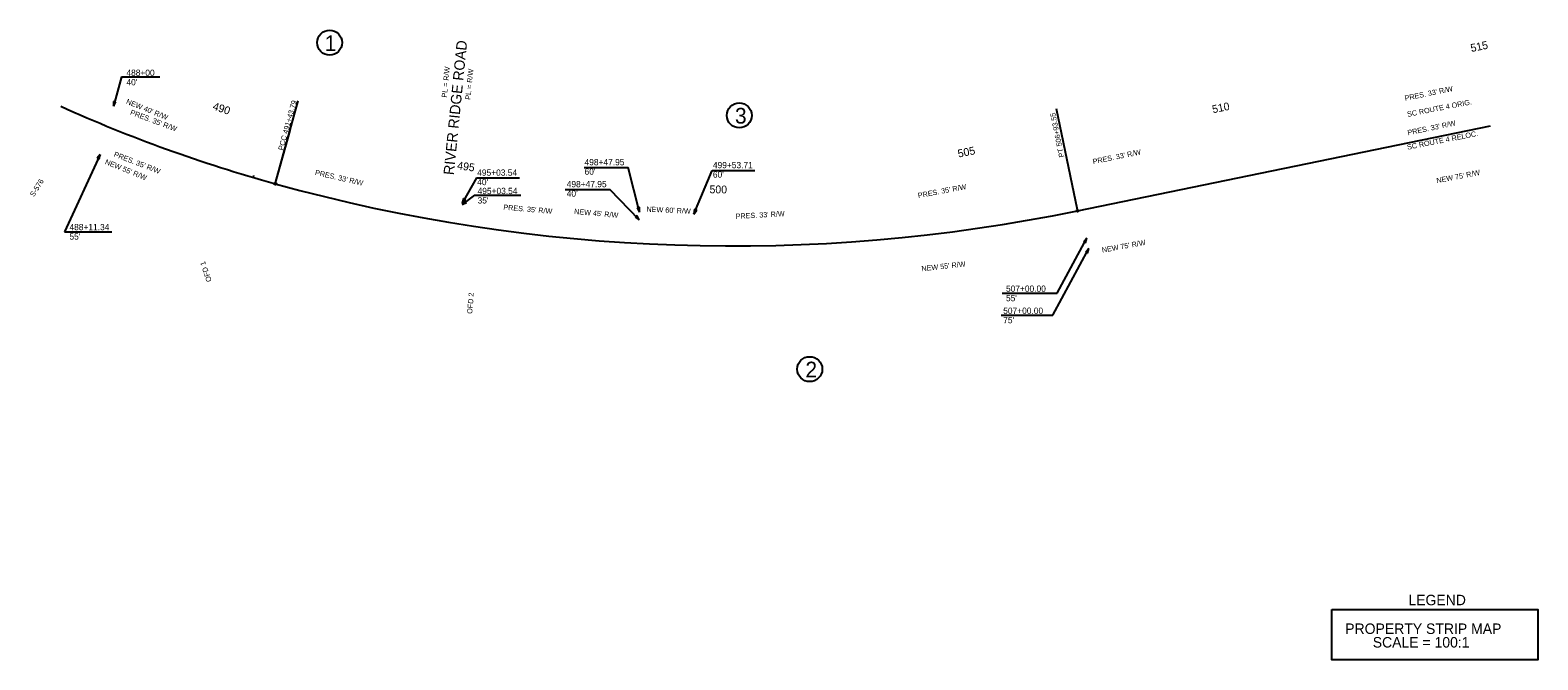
# Model space of a CAD drawing. Extents: x -64038 to -60878, y 1838 to 8465.
# Drawn here: x -63811 to -60927, y 1838 to 3043 of the extents above; entities that cross this region are included whole.
import ezdxf

# ---------------------------------------------------------------- set-up
doc = ezdxf.new("R2010")
doc.units = 0
for name, color, linetype in [('Level 1', 7, 'Continuous'), ('Level 13', 7, 'Continuous'), ('Level 19', 7, 'Continuous'), ('Level 21', 7, 'Continuous'), ('Level 24', 7, 'Continuous'), ('Level 25', 7, 'Continuous'), ('Level 33', 7, 'Continuous')]:
    doc.layers.add(name, color=color, linetype=linetype)

msp = doc.modelspace()

# ---------------------------------------------------------------- linework, layer by layer
at = {"layer": 'Level 1'}
msp.add_lwpolyline([(-61321.2, 1934.3), (-60927.4, 1934.3), (-60927.4, 1838.1), (-61321.2, 1838.1)], close=True, dxfattribs=at)
msp.add_circle((-63342.2, 2748.8), 2, dxfattribs=at)
msp.add_circle((-63342.2, 2748.8), 2, dxfattribs=at)
msp.add_circle((-63342.2, 2748.8), 2, dxfattribs=at)
msp.add_circle((-63342.2, 2748.8), 2, dxfattribs=at)
msp.add_circle((-63342.2, 2748.8), 2, dxfattribs=at)
msp.add_circle((-63342.2, 2748.8), 2, dxfattribs=at)
msp.add_circle((-63342.2, 2748.8), 2, dxfattribs=at)
msp.add_circle((-63342.2, 2748.8), 2, dxfattribs=at)
msp.add_circle((-63342.2, 2748.8), 2, dxfattribs=at)
msp.add_circle((-63342.2, 2748.8), 2, dxfattribs=at)
msp.add_circle((-63342.2, 2748.8), 2, dxfattribs=at)
msp.add_circle((-63342.2, 2748.8), 2, dxfattribs=at)
at = {"layer": 'Level 19'}
for p, q in [((-63341.7, 2750.7), (-63298.3, 2907.4)), ((-61808.2, 2699.1), (-61847.9, 2892.2)), ((-61807.8, 2697.2), (-61017.9, 2859.8)), ((-63341.7, 2750.7), (-63314.1, 2850.5)), ((-63341.7, 2750.7), (-63314.1, 2850.5)), ((-63384.3, 2760.8), (-63383.2, 2764.7)), ((-63342.2, 2748.8), (-63342.2, 2748.8))]:
    msp.add_line(p, q, dxfattribs=at)
for centre in [(-63342.2, 2748.8), (-61807.8, 2697.2)]:
    msp.add_circle(centre, 2, dxfattribs=at)
for centre, radius, start, end in [((-62577.2, 5509.6), 2864.8, 245.7732, 254.5124), ((-62468, 5904), 3274.1, 254.5125, 281.6332)]:
    msp.add_arc(centre, radius, start, end, dxfattribs=at)
at = {"layer": 'Level 24'}
for p, q in [((-63651.8, 2906.5), (-63652, 2897.2)), ((-63652, 2897.2), (-63647.5, 2905.3)), ((-63647.5, 2905.3), (-63651.8, 2906.5)), ((-62979, 2716.5), (-62984.9, 2709.3)), ((-62984.9, 2709.3), (-62976.3, 2712.9)), ((-62982.2, 2720.4), (-62984.6, 2711.5)), ((-62984.6, 2711.5), (-62978.2, 2718.3)), ((-62978.2, 2718.3), (-62982.2, 2720.4)), ((-62976.3, 2712.9), (-62979, 2716.5)), ((-62650.9, 2687.9), (-62654.1, 2684.8)), ((-62654.1, 2684.8), (-62646.2, 2679.9)), ((-62646.2, 2679.9), (-62650.9, 2687.9)), ((-62645.5, 2704.1), (-62649.9, 2703)), ((-62649.9, 2703), (-62645.4, 2694.8)), ((-62645.4, 2694.8), (-62645.5, 2704.1)), ((-62540.3, 2700), (-62541.7, 2690.8)), ((-62541.7, 2690.8), (-62536.1, 2698.2)), ((-62536.1, 2698.2), (-62540.3, 2700)), ((-61790.3, 2644.6), (-61796.6, 2637.8)), ((-61796.6, 2637.8), (-61792.6, 2635.6)), ((-61792.6, 2635.6), (-61790.3, 2644.6)), ((-61786.3, 2625), (-61792.6, 2618.2)), ((-61788.6, 2616), (-61786.3, 2625)), ((-61792.6, 2618.2), (-61788.6, 2616))]:
    msp.add_line(p, q, dxfattribs=at)
at = {"layer": 'Level 25'}
for centre in [(-63238.5, 3018.8), (-62454.9, 2879.7), (-62320, 2394.2)]:
    msp.add_circle(centre, 23.9, dxfattribs=at)
at = {"layer": 'Level 33'}
for p, q in [((-63636.8, 2953.3), (-63652, 2897.2)), ((-63636.8, 2953.3), (-63563.3, 2953.3)), ((-63677.5, 2805), (-63745.8, 2656.7)), ((-63677.5, 2805), (-63683.3, 2797.8)), ((-63683.3, 2797.8), (-63679.2, 2795.9)), ((-63679.2, 2795.9), (-63677.5, 2805)), ((-62751.7, 2780.1), (-62667.7, 2780.1)), ((-62645.4, 2694.8), (-62667.7, 2780.1)), ((-62541.7, 2690.8), (-62506.9, 2774.5)), ((-62506.9, 2774.5), (-62425.3, 2774.5)), ((-62957.8, 2760.1), (-62984.6, 2711.5)), ((-62957.8, 2760.1), (-62875.4, 2760.1)), ((-62961.1, 2727.2), (-62984.9, 2709.3)), ((-62961.1, 2727.2), (-62873, 2727.2)), ((-62788.2, 2738), (-62702.6, 2738)), ((-62646.2, 2679.9), (-62702.6, 2738)), ((-63745.8, 2656.7), (-63654.7, 2656.7)), ((-61855, 2497.2), (-61786.3, 2625)), ((-61846.8, 2539.4), (-61790.3, 2644.6)), ((-61952.2, 2539.4), (-61846.8, 2539.4)), ((-61954, 2497.2), (-61855, 2497.2))]:
    msp.add_line(p, q, dxfattribs=at)

# ---------------------------------------------------------------- texts
at = {"layer": 'Level 1'}
for s, rotation, p in [('OFD 1', 109.0008, (-63463.8, 2563.1)), ('OFD 2', 85.1043, (-62965.8, 2499.7))]:
    msp.add_text(s, height=10, rotation=rotation, dxfattribs=at).set_placement(p)
for s, p in [('LEGEND', (-61175, 1942.6)), ('PROPERTY STRIP MAP', (-61295.8, 1887.7)), ('SCALE = 100:1', (-61243.2, 1861.7))]:
    msp.add_text(s, height=20, dxfattribs=at).set_placement(p)
at = {"layer": 'Level 13'}
for s, rotation, p in [("PRES. 33' R/W", 11.6333, (-61181.1, 2907.4)), ("PRES. 35' R/W", 339.3421, (-63620.8, 2881.6)), ('SC ROUTE 4 ORIG.', 11.0953, (-61176.4, 2876.7)), ("PRES. 33' R/W", 11.6333, (-61175.7, 2841.5)), ('SC ROUTE 4 RELOC.', 11.0953, (-61176.5, 2813.9)), ("PRES. 35' R/W", 338.8367, (-63652.1, 2801.3)), ("PRES. 33' R/W", 11.6333, (-61777.8, 2786.2)), ("PRES. 33' R/W", 347.1087, (-63267.1, 2766)), ('S-576', 58.0243, (-63804.1, 2722.9)), ("PRES. 35' R/W", 10.7462, (-62112.3, 2721.3)), ("PRES. 35' R/W", 355.076, (-62906.5, 2699.3)), ("PRES. 33' R/W", 3.1894, (-62461.6, 2681.6))]:
    msp.add_text(s, height=10, rotation=rotation, dxfattribs=at).set_placement(p)
at = {"layer": 'Level 19'}
for s, rotation, p in [('PCC 491+43.79', 74.5124, (-63327.5, 2811.8)), ('PT 506+93.55', 101.6332, (-61833.1, 2800.4))]:
    msp.add_text(s, height=10, rotation=rotation, dxfattribs=at).set_placement(p)
at = {"layer": 'Level 21'}
for s, rotation, p in [('515', 11.6333, (-61054.5, 3000.8)), ('490', 341.6367, (-63463.3, 2891.1)), ('510', 11.6334, (-61548.7, 2883.7)), ('505', 11.6333, (-62035.3, 2798.9)), ('495', 351.6368, (-62995.1, 2777)), ('500', 359.4962, (-62511.8, 2730.7))]:
    msp.add_text(s, height=15, rotation=rotation, dxfattribs=at).set_placement(p)
at = {"layer": 'Level 25'}
for s, p in [('1', (-63247.9, 3002.8)), ('3', (-62463.1, 2864)), ('2', (-62328.3, 2378.5))]:
    msp.add_text(s, height=30, dxfattribs=at).set_placement(p)
for s, height, p in [('RIVER RIDGE ROAD', 20, (-63000.9, 2764.9)), ('PL = R/W', 10, (-63014.3, 2913.3)), ('PL = R/W', 10, (-62969.2, 2909.1))]:
    msp.add_text(s, height=height, rotation=84.2826, dxfattribs=at).set_placement(p)
at = {"layer": 'Level 33'}
for s, p in [('488+00', (-63627.1, 2955.2)), ("40'", (-63627.1, 2937.2)), ('495+03.54', (-62956.1, 2764.2)), ('498+47.95', (-62750.8, 2784.2)), ("60'", (-62750.8, 2766.2)), ('499+53.71', (-62505.3, 2778.6)), ("60'", (-62505.3, 2760.6)), ("40'", (-62956.1, 2746.2)), ('495+03.54', (-62955.4, 2729.1)), ('498+47.95', (-62784.9, 2742.2)), ("35'", (-62955.4, 2711.1)), ("40'", (-62784.9, 2724.2)), ('488+11.34', (-63736, 2660)), ("55'", (-63736, 2642)), ('507+00.00', (-61944.7, 2542.2)), ('507+00.00', (-61950, 2500)), ("55'", (-61944.7, 2524.2)), ("75'", (-61950, 2482))]:
    msp.add_text(s, height=12, dxfattribs=at).set_placement(p)
for s, rotation, p in [("NEW 40' R/W", 337.7515, (-63628.6, 2902.5)), ("NEW 55' R/W", 337.7515, (-63669, 2787.1)), ("NEW 75' R/W", 10.9187, (-61120.4, 2749.9)), ("NEW 45' R/W", 354.754, (-62771.1, 2691.3)), ("NEW 60' R/W", 357.2094, (-62632.6, 2695.5)), ("NEW 75' R/W", 10.3064, (-61760.4, 2616.9)), ("NEW 55' R/W", 6.1735, (-62105.9, 2581.5))]:
    msp.add_text(s, height=10, rotation=rotation, dxfattribs=at).set_placement(p)

doc.saveas('drawing.dxf')
